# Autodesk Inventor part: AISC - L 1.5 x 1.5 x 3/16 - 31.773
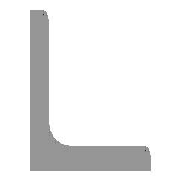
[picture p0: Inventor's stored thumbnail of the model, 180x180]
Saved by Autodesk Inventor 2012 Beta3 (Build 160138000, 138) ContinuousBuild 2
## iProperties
IsCustomPart: 1
Created: 2010-11
Part Number: AISC - L 1.5 x 1.5 x 3/16 - 31.773
Material: Steel, Mild
Description: Angle Steel
Document SubType Name: Modeling
Standard: ANSI
Designer: Beta-8540w
Standards Organization: ANSI
Language: en-US
Size Designation: L 1.5 x 1.5 x 3/16
Categories: <MemberInstance><Categories><Category DisplayName="Structural Shapes" InternalName="089c4875-fa83-4c05-b084-43b9cc11f5ed" Mnemonic="GRDR"><CategoryParameter Dis
Stock Number: L 1.5 x 1.5 x 3/16
Density: 7.86 g/cm^3
G_L: 31.773 in
G_W: 1.500 in
G_H: 1.500 in
+B44689CE-99D4-45E6-A613-DBAE9BF7CE7B+CUTDETAIL1: Cut
_CCFamilyMember: 5
_CCFamilyDisplayName: ANSI L (Equal angles) - Angle Steel
_FrameMemberDoc: Frame Member File
_Version: 15.0.0
_GetPNFromCC: 1
Author: Beta-8540w
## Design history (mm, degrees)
node "Start plane"
node "End plane"
sketch "Sketch"
  geometry: L1 (38.1, 0)-(0, 0); L2 (0, 0)-(0, 38.1); L3 (0, 38.1)-(2.476, 38.1); L4 (4.762, 35.814)-(4.762, 9.589); L5 (9.588, 4.763)-(35.814, 4.763); L6 (38.1, 2.477)-(38.1, 0); L7 (0, -11.041)-(0, 31.538); L8 (-11.041, 0)-(31.538, 0); L9 (0, 48.496)-(0, -20.964) reference; L10 (-20.964, 0)-(48.496, 0) reference; A1 r 4.826 centre (9.588, 9.589) between (4.762, 9.589) and (9.588, 4.763); A2 r 2.286 centre (2.476, 35.814) between (4.762, 35.814) and (2.476, 38.1); A3 r 2.286 centre (35.814, 2.477) between (38.1, 2.477) and (35.814, 4.763); 3 further points
  constraints: 16 end point, 6 point on circle, 6 point on line, 6 tangent, 4 parallel, 3 centre point, 2 collinear, 1 equal radius, 1 horizontal, 1 perpendicular
  dimensions: "d0" = 38.1 distance between parallel lines of L6 L2 (= G_H); "d1" = 38.1 distance between parallel lines of L3 L1 (= G_H); "d2" = 4.7625 distance between parallel lines of L2 L4 (= G_T); "d3" = 4.7625 distance between parallel lines of L1 L5 (= G_T); "d10" = 0 distance between parallel lines of L7 L2 (computed from ex); "d11" = 0 distance between parallel lines of L8 L1 (computed from d10); "d14" = 4.826 radius of A1 (= G_IR); "d15" = 2.286 radius of A2 (= G_ER)
extrude "Body" new body sketch "Sketch" stored distance "d4" = 807.0404 (= G_L); taper "d5" = 0 deg
node "Driven Length"
  sketch "Sketch3"
    geometry: L1 (0, 0)-(10, 0) reference
    constraints: 2 end point, 1 horizontal
  workplane "Work Plane3"
  sketch "Sketch4"
    geometry: L1 (-2, 0)-(12, 0) reference; L2 (-2, 807.04)-(12, 807.04) reference
    dimensions: "d17" = 807.0404 distance between parallel lines of L1 L2 (derived)
workplane "Work Plane4"
split "Split1"
body "Solid1"
other parameters: "G_H" = 38.1 [user parameter; used in 2 equation terms], "G_T" = 4.7625 [user parameter; used in 2 equation terms], "G_ER" = 2.286 [user parameter; used in 1 equation term], "G_IR" = 4.826 [user parameter; used in 1 equation term], "G_L" = 807.0404 (= d17) [user parameter; used in 1 equation term], "ex" = 0 [user parameter; used in 1 equation term], "G_OFFSET_START" = 0 [user parameter; used in 1 equation term], "G_OFFSET_END" = -29.72503 [user parameter; used in 1 equation term], "d12" = 0 (computed from G_OFFSET_START), "d13" = 807.0404 (= G_OFFSET_END + B_L), "B_L" = 836.76542 [user parameter; used in 1 equation term], "d16" = 90 deg, "MAS" = 0.26787 [user parameter]
